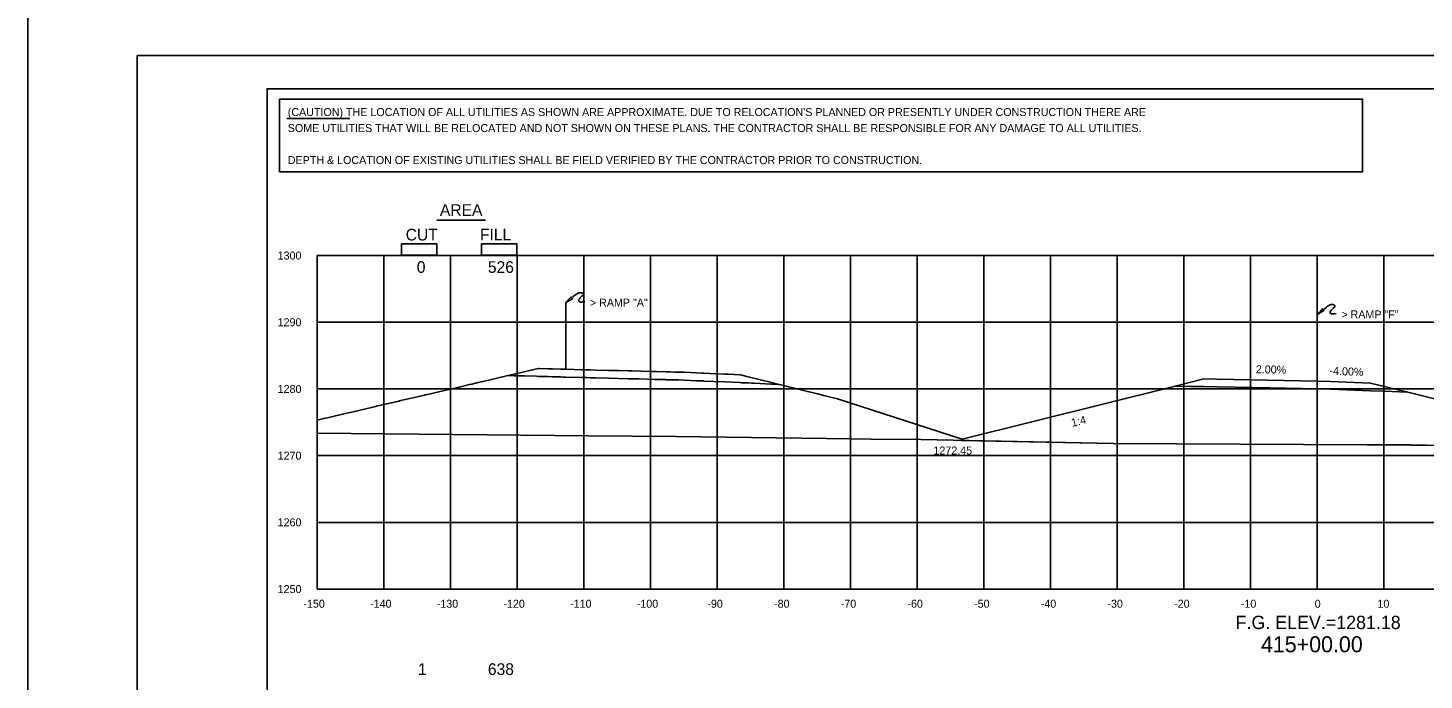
# Model space of a CAD drawing. Extents: x 2148105 to 2149976, y 144169 to 149705.
# Drawn here: x 2148219.9 to 2148429.3, y 146483.3 to 146581 of the extents above; entities that cross this region are included whole.
import ezdxf

# ---------------------------------------------------------------- set-up
doc = ezdxf.new("R2010")
doc.units = 0
for name, color, linetype in [('Bridge M-Header', 7, 'Continuous'), ('Default', 7, 'Continuous'), ('INR_Tracking', 7, 'Continuous'), ('PH1a-2-RampC', 7, 'Continuous'), ('PH1a-PR-DividingStrip', 7, 'Continuous'), ('PH1a-PR-ServRd', 7, 'Continuous'), ('PH2-PR-Barrier', 7, 'Continuous'), ('PR-AttenuatorPad', 7, 'Continuous'), ('PR_Align_PC', 7, 'Continuous'), ('PR_Align_Ramp_E', 7, 'Continuous'), ('PR_Align_Ramp_J', 7, 'Continuous'), ('PR_Storm_Channel', 7, 'Continuous'), ('PR_Storm_Conc_Box_PH1B', 7, 'Continuous'), ('PR_Storm_Conc_Pipe', 7, 'Continuous'), ('PR_Storm_Conc_Pipe_PH1B', 7, 'Continuous'), ('PR_Storm_Inlet_CICI_PH1B', 7, 'Continuous'), ('PR_Storm_Junction_Box_PH1B', 7, 'Continuous'), ('PR_Storm_MH', 7, 'Continuous'), ('PR_Storm_MH_PH1B', 7, 'Continuous'), ('PR_Storm_Standard_Median_Drain_PH1B', 7, 'Continuous'), ('PR_Storm_Txt_PH1B', 7, 'Continuous'), ('TopCut', 7, 'Continuous'), ('TOPO_BRIDGE_Pier Cap', 7, 'Continuous')]:
    doc.layers.add(name, color=color, linetype=linetype)

# ---------------------------------------------------------------- blocks, each defined once
blk = doc.blocks.new('POINT_DISPLAY')
at = {"layer": 'Default'}
blk.add_line((0, 0), (0, 0), dxfattribs=at)

msp = doc.modelspace()

# ---------------------------------------------------------------- linework, layer by layer
at = {"layer": 'INR_Tracking'}
msp.add_lwpolyline([(2148360.08, 146519.36), (2148392, 146527.34), (2148394.33, 146527.3), (2148394.33, 146527.3), (2148394.81, 146527.29), (2148396.32, 146527.26), (2148396.32, 146527.26), (2148398.32, 146527.22), (2148406.22, 146527.06), (2148413.32, 146526.92), (2148415.32, 146526.88), (2148415.32, 146526.88), (2148421.31, 146526.64), (2148421.32, 146526.64), (2148423.31, 146526.56), (2148423.31, 146526.56), (2148426.87, 146526.41), (2148426.88, 146526.41), (2148437.11, 146523.86)], dxfattribs=at)
at = {"layer": 'PH1a-PR-ServRd'}
msp.add_lwpolyline([(2148570.82, 146361.91), (2148255.82, 146361.91), (2148255.82, 146571.91), (2148570.82, 146571.91)], close=True, dxfattribs=at)
at = {"layer": 'PH2-PR-Barrier'}
msp.add_line((2148413.32, 146528.08), (2148413.32, 146538.08), dxfattribs=at)
for points in [[(2148413.32, 146538.08), (2148413.84, 146538.63), (2148414.1, 146538.94), (2148414.18, 146538.77), (2148414.32, 146538.66), (2148413.32, 146538.08)], [(2148414.33, 146538.89), (2148414.69, 146539.19), (2148414.85, 146539.31), (2148414.94, 146539.39), (2148415.04, 146539.44), (2148415.14, 146539.49), (2148415.26, 146539.53), (2148415.39, 146539.56), (2148415.49, 146539.57), (2148415.57, 146539.57), (2148415.65, 146539.56), (2148415.72, 146539.55), (2148415.78, 146539.53), (2148415.83, 146539.51), (2148415.87, 146539.49), (2148415.91, 146539.45), (2148415.95, 146539.41), (2148415.98, 146539.35), (2148415.97, 146539.3), (2148415.96, 146539.26), (2148415.91, 146539.19), (2148415.72, 146539.03), (2148415.53, 146538.86), (2148415.46, 146538.79), (2148415.39, 146538.71), (2148415.33, 146538.62), (2148415.29, 146538.56), (2148415.25, 146538.47), (2148415.25, 146538.39), (2148415.27, 146538.31), (2148415.31, 146538.24), (2148415.36, 146538.2), (2148415.42, 146538.18), (2148415.53, 146538.16), (2148415.66, 146538.17), (2148415.82, 146538.19), (2148416.15, 146538.22)]]:
    msp.add_lwpolyline(points, dxfattribs=at)
at = {"layer": 'PR-AttenuatorPad'}
msp.add_line((2148300.63, 146529.85), (2148300.63, 146539.85), dxfattribs=at)
for points in [[(2148300.63, 146539.85), (2148301.14, 146540.4), (2148301.4, 146540.71), (2148301.49, 146540.54), (2148301.63, 146540.43), (2148300.63, 146539.85)], [(2148301.64, 146540.66), (2148301.99, 146540.96), (2148302.15, 146541.08), (2148302.25, 146541.16), (2148302.35, 146541.21), (2148302.45, 146541.26), (2148302.56, 146541.3), (2148302.7, 146541.33), (2148302.79, 146541.34), (2148302.87, 146541.34), (2148302.96, 146541.33), (2148303.03, 146541.32), (2148303.08, 146541.3), (2148303.14, 146541.28), (2148303.18, 146541.26), (2148303.22, 146541.22), (2148303.25, 146541.18), (2148303.28, 146541.12), (2148303.28, 146541.07), (2148303.27, 146541.03), (2148303.21, 146540.96), (2148303.02, 146540.8), (2148302.84, 146540.63), (2148302.76, 146540.56), (2148302.7, 146540.48), (2148302.64, 146540.39), (2148302.6, 146540.33), (2148302.56, 146540.24), (2148302.55, 146540.16), (2148302.57, 146540.08), (2148302.62, 146540.01), (2148302.67, 146539.97), (2148302.72, 146539.95), (2148302.83, 146539.93), (2148302.97, 146539.94), (2148303.12, 146539.96), (2148303.46, 146539.99)]]:
    msp.add_lwpolyline(points, dxfattribs=at)
at = {"layer": 'PR_Align_PC'}
msp.add_line((2148281.28, 146552.21), (2148288.56, 146552.21), dxfattribs=at)
for points in [[(2148275.98, 146548.66), (2148281.29, 146548.66), (2148281.29, 146546.97), (2148275.98, 146546.97)], [(2148275.98, 146548.66), (2148281.29, 146548.66), (2148281.29, 146546.97), (2148275.98, 146546.97)], [(2148287.98, 146548.66), (2148293.29, 146548.66), (2148293.29, 146546.97), (2148287.98, 146546.97)], [(2148287.98, 146548.66), (2148293.29, 146548.66), (2148293.29, 146546.97), (2148287.98, 146546.97)]]:
    msp.add_lwpolyline(points, close=True, dxfattribs=at)
at = {"layer": 'PR_Align_Ramp_E'}
msp.add_lwpolyline([(2148219.95, 146585.16), (2148579.95, 146585.16), (2148579.95, 146345.16), (2148219.95, 146345.16)], close=True, dxfattribs=at)
at = {"layer": 'PR_Align_Ramp_J'}
msp.add_lwpolyline([(2148236.32, 146576.91), (2148576.32, 146576.91), (2148576.32, 146356.91), (2148236.32, 146356.91)], close=True, dxfattribs=at)
at = {"layer": 'PR_Storm_Channel'}
msp.add_lwpolyline([(2148392, 146527.34), (2148396.32, 146528.42), (2148398.32, 146528.38), (2148413.32, 146528.08), (2148415.32, 146528.04), (2148421.32, 146527.8), (2148426.88, 146526.41)], dxfattribs=at)
at = {"layer": 'PR_Storm_Conc_Box_PH1B'}
for p, q in [((2148263.32, 146546.91), (2148563.32, 146546.91)), ((2148263.32, 146496.91), (2148263.32, 146546.91)), ((2148273.32, 146496.91), (2148273.32, 146546.91)), ((2148283.32, 146496.91), (2148283.32, 146546.91)), ((2148293.32, 146496.91), (2148293.32, 146546.91)), ((2148303.32, 146496.91), (2148303.32, 146546.91)), ((2148313.32, 146496.91), (2148313.32, 146546.91)), ((2148323.32, 146496.91), (2148323.32, 146546.91)), ((2148333.32, 146496.91), (2148333.32, 146546.91)), ((2148343.32, 146496.91), (2148343.32, 146546.91)), ((2148353.32, 146496.91), (2148353.32, 146546.91)), ((2148363.32, 146496.91), (2148363.32, 146546.91)), ((2148373.32, 146496.91), (2148373.32, 146546.91)), ((2148383.32, 146496.91), (2148383.32, 146546.91)), ((2148393.32, 146496.91), (2148393.32, 146546.91)), ((2148403.32, 146496.91), (2148403.32, 146546.91)), ((2148413.32, 146496.91), (2148413.32, 146546.91)), ((2148423.32, 146496.91), (2148423.32, 146546.91)), ((2148263.32, 146536.91), (2148563.32, 146536.91)), ((2148263.32, 146526.91), (2148563.32, 146526.91)), ((2148263.32, 146516.91), (2148563.32, 146516.91)), ((2148263.32, 146506.91), (2148563.32, 146506.91)), ((2148263.32, 146496.91), (2148563.32, 146496.91))]:
    msp.add_line(p, q, dxfattribs=at)
at = {"layer": 'PR_Storm_Conc_Pipe'}
msp.add_lwpolyline([(2148263.32, 146522.23), (2148264.53, 146522.52), (2148264.88, 146522.6), (2148265.27, 146522.69), (2148267.33, 146523.17), (2148268.75, 146523.5), (2148269.79, 146523.74), (2148270.21, 146523.84), (2148271.86, 146524.23), (2148272.23, 146524.31), (2148275.57, 146525.09), (2148275.69, 146525.12), (2148275.72, 146525.13), (2148275.88, 146525.17), (2148275.89, 146525.17), (2148278.59, 146525.8), (2148279.2, 146525.94), (2148279.47, 146526), (2148279.55, 146526.02), (2148280.11, 146526.15), (2148281.57, 146526.49), (2148282.23, 146526.65), (2148282.68, 146526.75), (2148284.6, 146527.2), (2148286.17, 146527.56), (2148286.52, 146527.65), (2148287.25, 146527.81), (2148289.25, 146528.28), (2148289.65, 146528.37), (2148291.94, 146528.91), (2148292.93, 146528.88), (2148293.04, 146528.88), (2148293.13, 146528.88), (2148294.37, 146528.85), (2148296.21, 146528.8), (2148296.45, 146528.79), (2148296.61, 146528.79), (2148297.91, 146528.76), (2148298.6, 146528.74), (2148299.8, 146528.71), (2148300.1, 146528.7), (2148300.34, 146528.69), (2148300.63, 146528.69), (2148303.04, 146528.63), (2148303.58, 146528.61), (2148303.72, 146528.61), (2148304.28, 146528.59), (2148305.07, 146528.57), (2148307.06, 146528.52), (2148308.5, 146528.49), (2148309.96, 146528.45), (2148310.32, 146528.44), (2148310.55, 146528.43), (2148311.59, 146528.41), (2148314.03, 146528.35), (2148315.57, 146528.31), (2148315.64, 146528.3), (2148316.29, 146528.29), (2148317.51, 146528.26), (2148318.38, 146528.23), (2148320.22, 146528.15), (2148320.99, 146528.12), (2148321.21, 146528.11), (2148321.32, 146528.1), (2148322.8, 146528.04), (2148324.48, 146527.96), (2148326.73, 146527.86), (2148327, 146527.85), (2148327.24, 146527.84), (2148327.96, 146527.81), (2148328.49, 146527.78), (2148328.8, 146527.77), (2148331.44, 146527.65), (2148332.53, 146527.6), (2148332.68, 146527.57), (2148334.44, 146527.13), (2148334.92, 146527.01), (2148336.45, 146526.64), (2148338.36, 146526.17), (2148338.39, 146526.16), (2148338.41, 146526.16), (2148339.24, 146525.95), (2148341.34, 146525.44), (2148360.08, 146519.36)], dxfattribs=at)
at = {"layer": 'PR_Storm_Conc_Pipe_PH1B'}
msp.add_lwpolyline([(2148255.82, 146361.91), (2148570.82, 146361.91), (2148570.82, 146571.91), (2148255.82, 146571.91)], close=True, dxfattribs=at)
msp.add_lwpolyline([(2148255.82, 146361.91), (2148570.82, 146361.91), (2148570.82, 146571.91), (2148255.82, 146571.91)], close=True, dxfattribs=at)
at = {"layer": 'PR_Storm_Inlet_CICI_PH1B'}
msp.add_lwpolyline([(2148263.32, 146520.3), (2148304, 146519.89), (2148317.18, 146519.76), (2148343.5, 146519.42), (2148346.42, 146519.37), (2148353.89, 146519.32), (2148382.73, 146518.72), (2148420.76, 146518.54), (2148425.63, 146518.52), (2148428.9, 146518.49), (2148464.35, 146517.79), (2148474.09, 146517.5), (2148492.71, 146517.04), (2148496.08, 146517.04), (2148515.43, 146516.36), (2148533.07, 146515.82), (2148536.41, 146515.73), (2148563.32, 146514.61)], dxfattribs=at)
at = {"layer": 'PR_Storm_MH'}
msp.add_line((2148258.8, 146567.46), (2148268.21, 146567.46), dxfattribs=at)
msp.add_lwpolyline([(2148257.69, 146570.34), (2148420.12, 146570.34), (2148420.12, 146559.47), (2148257.69, 146559.47)], close=True, dxfattribs=at)
at = {"layer": 'PR_Storm_Standard_Median_Drain_PH1B'}
for q in [(2148263.32, 146546.91), (2148563.32, 146496.91)]:
    msp.add_line((2148263.32, 146496.91), q, dxfattribs=at)
at = {"layer": 'PR_Storm_Txt_PH1B'}
msp.add_lwpolyline([(2148291.94, 146528.91), (2148292.93, 146529.14), (2148293.08, 146529.17), (2148293.13, 146529.19), (2148296.45, 146529.96), (2148296.54, 146529.96), (2148296.61, 146529.96), (2148297.91, 146529.92), (2148298.6, 146529.91), (2148299.8, 146529.87), (2148300.1, 146529.87), (2148300.34, 146529.86), (2148300.63, 146529.85), (2148303.04, 146529.79), (2148303.58, 146529.78), (2148304.13, 146529.76), (2148304.28, 146529.76), (2148305.07, 146529.74), (2148307.06, 146529.69), (2148308.5, 146529.65), (2148309.96, 146529.62), (2148310.19, 146529.61), (2148310.54, 146529.6), (2148313.38, 146529.53), (2148314.03, 146529.51), (2148314.24, 146529.51), (2148315.64, 146529.47), (2148315.71, 146529.47), (2148316.29, 146529.45), (2148316.93, 146529.44), (2148317.51, 146529.42), (2148318.38, 146529.4), (2148320.22, 146529.32), (2148320.99, 146529.28), (2148321.1, 146529.28), (2148321.32, 146529.27), (2148323.11, 146529.19), (2148324.48, 146529.13), (2148325, 146529.11), (2148326.73, 146529.03), (2148327, 146528.96), (2148327.78, 146528.77), (2148327.96, 146528.73), (2148329.81, 146528.27), (2148331.44, 146527.87), (2148331.63, 146527.82), (2148332.53, 146527.6)], dxfattribs=at)
at = {"layer": 'TopCut'}
for points in [[(2148287.98, 146546.97), (2148293.29, 146546.97), (2148293.29, 146548.66), (2148287.98, 146548.66), (2148287.98, 146546.97)], [(2148437.11, 146523.86), (2148426.88, 146526.41), (2148426.87, 146526.41), (2148423.31, 146526.56), (2148423.31, 146526.56), (2148421.32, 146526.64), (2148421.31, 146526.64), (2148415.32, 146526.88), (2148415.32, 146526.88), (2148413.32, 146526.92), (2148406.22, 146527.06), (2148398.32, 146527.22), (2148396.32, 146527.26), (2148396.32, 146527.26), (2148394.81, 146527.29), (2148394.33, 146527.3), (2148394.33, 146527.3), (2148392, 146527.34), (2148360.08, 146519.36), (2148360.08, 146519.19), (2148382.73, 146518.72), (2148420.76, 146518.54), (2148426.45, 146518.51), (2148426.47, 146518.51), (2148426.48, 146518.51), (2148426.5, 146518.51), (2148426.52, 146518.51), (2148426.54, 146518.51), (2148426.56, 146518.51), (2148426.58, 146518.51), (2148426.61, 146518.51), (2148426.63, 146518.51), (2148426.67, 146518.51), (2148426.68, 146518.51), (2148426.74, 146518.51), (2148426.75, 146518.51), (2148426.81, 146518.51), (2148426.83, 146518.51), (2148426.91, 146518.51), (2148426.92, 146518.51), (2148426.93, 146518.51), (2148427.03, 146518.51), (2148427.03, 146518.51), (2148427.18, 146518.51), (2148427.18, 146518.51), (2148427.36, 146518.5), (2148427.38, 146518.5), (2148427.6, 146518.5), (2148427.64, 146518.5), (2148427.94, 146518.5), (2148428.03, 146518.5), (2148428.46, 146518.49), (2148428.63, 146518.49), (2148428.9, 146518.49), (2148429.3, 146518.48), (2148429.68, 146518.47)]]:
    msp.add_lwpolyline(points, dxfattribs=at)
at = {"layer": 'TOPO_BRIDGE_Pier Cap'}
msp.add_lwpolyline([(2148275.98, 146546.97), (2148281.29, 146546.97), (2148281.29, 146548.66), (2148275.98, 146548.66), (2148275.98, 146546.97)], dxfattribs=at)

# ---------------------------------------------------------------- block references
at = {"layer": 'PR_Storm_Conc_Pipe_PH1B', "xscale": 10, "yscale": 10}
for p in [(2148398.32, 146528.38), (2148398.32, 146528.38), (2148415.32, 146528.04), (2148415.32, 146528.04), (2148421.32, 146527.8), (2148421.32, 146527.8)]:
    msp.add_blockref('POINT_DISPLAY', p, dxfattribs=at)

# ---------------------------------------------------------------- texts
at = {"layer": 'Bridge M-Header'}
for s, rotation, p in [('2.00%', 358.8542, (2148404.09, 146529.27)), ('-4.00%', 357.7094, (2148415.13, 146529.05))]:
    msp.add_text(s, height=1.2, rotation=rotation, dxfattribs=at).set_placement(p)
at = {"layer": 'PH1a-2-RampC'}
msp.add_text('1272.45', height=1.2, dxfattribs=at).set_placement((2148355.75, 146517.08))
at = {"layer": 'PH1a-PR-DividingStrip'}
msp.add_text('1:4', height=1.2, rotation=14.0349, dxfattribs=at).set_placement((2148376.58, 146521.22))
at = {"layer": 'PH2-PR-Barrier'}
msp.add_text('> RAMP "F"', height=1.2, rotation=360, dxfattribs=at).set_placement((2148416.92, 146537.48))
at = {"layer": 'PR-AttenuatorPad'}
msp.add_text('> RAMP "A"', height=1.2, rotation=360, dxfattribs=at).set_placement((2148304.23, 146539.25))
at = {"layer": 'PR_Align_PC'}
for s, p in [('AREA', (2148281.74, 146552.86)), ('CUT', (2148276.6, 146549.17)), ('FILL', (2148287.74, 146549.17)), ('0', (2148278.27, 146544.31)), ('526', (2148288.93, 146544.31)), ('1', (2148278.44, 146484.03)), ('638', (2148288.93, 146484.03))]:
    msp.add_text(s, height=1.75, dxfattribs=at).set_placement(p)
at = {"layer": 'PR_Storm_Junction_Box_PH1B'}
msp.add_text('415+00.00', height=2.4, dxfattribs=at).set_placement((2148404.87, 146487.43))
at = {"layer": 'PR_Storm_MH'}
for s, p in [("(CAUTION) THE LOCATION OF ALL UTILITIES AS SHOWN ARE APPROXIMATE. DUE TO RELOCATION'S PLANNED OR PRESENTLY UNDER CONSTRUCTION THERE ARE ", (2148258.92, 146567.82)), ('SOME UTILITIES THAT WILL BE RELOCATED AND NOT SHOWN ON THESE PLANS. THE CONTRACTOR SHALL BE RESPONSIBLE FOR ANY DAMAGE TO ALL UTILITIES.', (2148258.92, 146565.42)), ('DEPTH & LOCATION OF EXISTING UTILITIES SHALL BE FIELD VERIFIED BY THE CONTRACTOR PRIOR TO CONSTRUCTION.', (2148258.92, 146560.62))]:
    msp.add_text(s, height=1.2, dxfattribs=at).set_placement(p)
at = {"layer": 'PR_Storm_MH_PH1B'}
for s, height, p in [('1300', 1.2, (2148257.4, 146546.31)), ('1290', 1.2, (2148257.4, 146536.31)), ('1280', 1.2, (2148257.4, 146526.31)), ('1270', 1.2, (2148257.4, 146516.31)), ('1260', 1.2, (2148257.4, 146506.31)), ('1250', 1.2, (2148257.4, 146496.31)), ('-150', 1.2, (2148261.26, 146494.11)), ('-140', 1.2, (2148271.26, 146494.11)), ('-130', 1.2, (2148281.26, 146494.11)), ('-120', 1.2, (2148291.26, 146494.11)), ('-110', 1.2, (2148301.26, 146494.11)), ('-100', 1.2, (2148311.26, 146494.11)), ('-90', 1.2, (2148321.85, 146494.11)), ('-80', 1.2, (2148331.85, 146494.11)), ('-70', 1.2, (2148341.85, 146494.11)), ('-60', 1.2, (2148351.85, 146494.11)), ('-50', 1.2, (2148361.85, 146494.11)), ('-40', 1.2, (2148371.85, 146494.11)), ('-30', 1.2, (2148381.85, 146494.11)), ('-20', 1.2, (2148391.85, 146494.11)), ('-10', 1.2, (2148401.85, 146494.11)), ('0', 1.2, (2148412.93, 146494.11)), ('10', 1.2, (2148422.34, 146494.11)), ('F.G. ELEV.=1281.18', 2, (2148401.07, 146490.91))]:
    msp.add_text(s, height=height, dxfattribs=at).set_placement(p)

doc.saveas('drawing.dxf')
